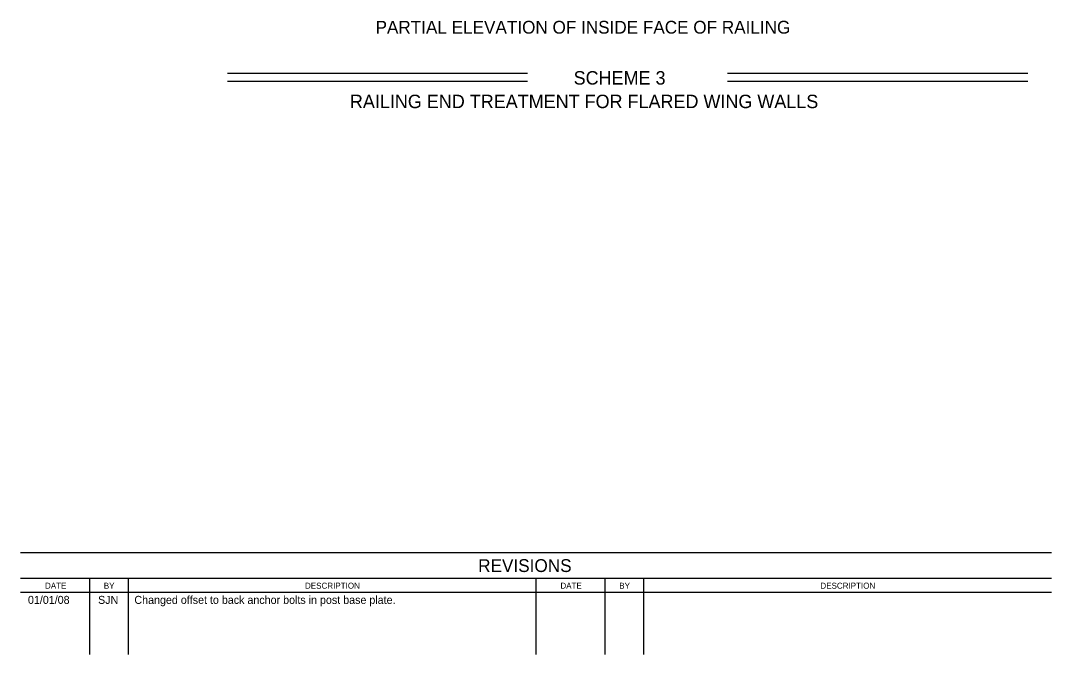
# Model space of a CAD drawing. Extents: x 21652.5 to 21723.2, y 56079.2 to 56117.9.
# Drawn here: x 21653.8 to 21674.42, y 56079.22 to 56091.89 of the extents above; entities that cross this region are included whole.
import ezdxf

# ---------------------------------------------------------------- set-up
doc = ezdxf.new("R2010")
doc.units = 0
for name, color, linetype in [('Border', 7, 'Continuous'), ('Dimension', 7, 'Continuous'), ('TextStructures', 7, 'Continuous')]:
    doc.layers.add(name, color=color, linetype=linetype)

msp = doc.modelspace()

# ---------------------------------------------------------------- linework, layer by layer
at = {"layer": 'Border'}
for p, q in [((21674.416, 56081.251), (21653.804, 56081.251)), ((21674.416, 56080.736), (21653.804, 56080.736)), ((21655.181, 56080.736), (21655.181, 56079.221)), ((21655.954, 56080.736), (21655.954, 56079.221)), ((21664.11, 56080.736), (21664.11, 56079.221)), ((21665.487, 56080.736), (21665.487, 56079.221)), ((21666.261, 56080.736), (21666.261, 56079.221)), ((21653.804, 56080.463), (21674.416, 56080.463))]:
    msp.add_line(p, q, dxfattribs=at)
at = {"layer": 'Dimension'}
for p, q in [((21657.938, 56090.834), (21663.942, 56090.834)), ((21667.942, 56090.834), (21673.942, 56090.834)), ((21657.938, 56090.676), (21663.942, 56090.676)), ((21667.942, 56090.676), (21673.942, 56090.676))]:
    msp.add_line(p, q, dxfattribs=at)

# ---------------------------------------------------------------- texts
for s, p in [('SCHEME 3', (21664.863, 56090.609)), ('RAILING END TREATMENT FOR FLARED WING WALLS', (21660.389, 56090.138))]:
    msp.add_text(s, height=0.2688, dxfattribs=at).set_placement(p)
at = {"layer": 'TextStructures'}
for s, height, p in [('PARTIAL ELEVATION OF INSIDE FACE OF RAILING', 0.256, (21660.902, 56091.627)), ('REVISIONS', 0.2567, (21662.953, 56080.867)), ('BY', 0.1201, (21655.468, 56080.533)), ('BY', 0.1201, (21665.775, 56080.533)), ('01/01/08', 0.16, (21653.951, 56080.23)), ('SJN', 0.16, (21655.353, 56080.23)), ('Changed offset to back anchor bolts in post base plate.', 0.16, (21656.08, 56080.23))]:
    msp.add_text(s, height=height, dxfattribs=at).set_placement(p)
for s, height, rotation, p in [('DATE', 0.1196, 359.8693, (21654.293, 56080.534)), ('DESCRIPTION', 0.12007, 0.0498, (21659.491, 56080.533)), ('DATE', 0.1196, 359.8693, (21664.599, 56080.534)), ('DESCRIPTION', 0.12007, 0.0498, (21669.797, 56080.533))]:
    msp.add_text(s, height=height, rotation=rotation, dxfattribs=at).set_placement(p)

doc.saveas('drawing.dxf')
